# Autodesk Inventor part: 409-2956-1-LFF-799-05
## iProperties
Created: 2010-11
Part Number: 409-2956-1-LFF-799-05
Material: 3/4" OD TUBE - SS
Document SubType Name: Modeling
Designer: S. Boerckel
Engineer: Steve Boerckel
Mass: 753.846 g
Surface Area: 1132 cm^2
Volume: 93.2978 cm^3
Density: 8.08 g/cm^3
Description: DRAIN TUBING
LGTH: 40.702 in
Author: S. Boerckel
Revision Number: 0
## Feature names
1. TaggingFeature1
